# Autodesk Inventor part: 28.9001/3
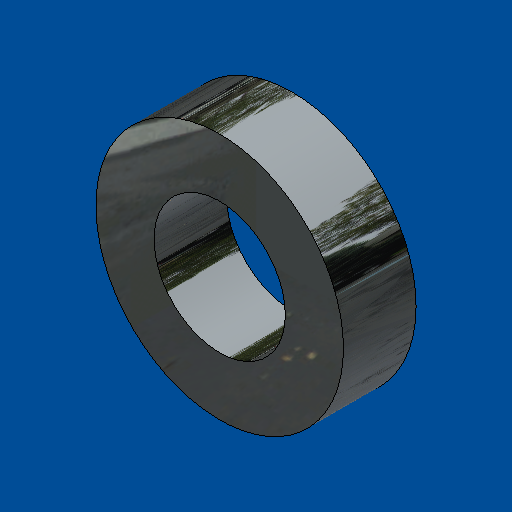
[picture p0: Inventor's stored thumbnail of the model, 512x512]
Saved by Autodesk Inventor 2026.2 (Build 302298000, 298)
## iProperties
Created: 2022-07
Part Number: 28.9001/3
Material: Aluminum 6061
Document SubType Name: Modeling
Designer: amoles
Density: 2.7 g/cm^3
Appearance: Zinc
Stock Number: 3/4" 6061 AL ROD
Description: ROTATIONAL ELEMENT WASHER
Vendor: F
Mass: 3.5693 g
Surface Area: 10.0063 cm^2
Volume: 1.32196 cm^3
Author: amoles
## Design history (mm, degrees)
sketch "Sketch1"
  geometry: C1 r 5.05 at (0, 0); C2 r 9.525 at (0, 0); 1 further point
  constraints: 2 centre point, 2 coincident
  dimensions: "d0" = 10.1 diameter of C1; "d1" = 19.05 diameter of C2
extrude "Extrusion1" new body sketch "Sketch1" distance "d2" = 5.588; taper "d3" = 0 deg
body "Solid1"
